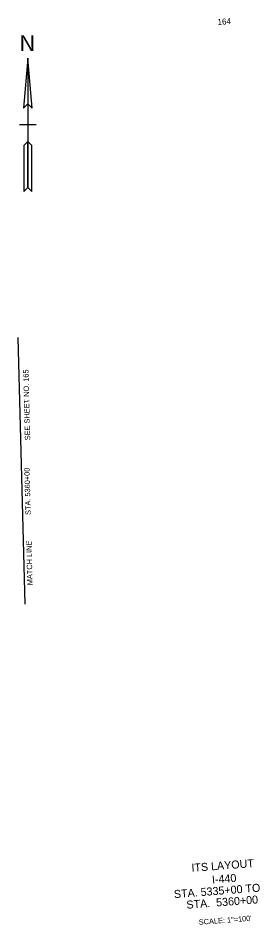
# Model space of a CAD drawing. Extents: x -200 to 1750512, y -325 to 653817.
# Drawn here: x 1749969 to 1750512, y 651778 to 653817 of the extents above; entities that cross this region are included whole.
import ezdxf

# ---------------------------------------------------------------- set-up
doc = ezdxf.new("R2010")
doc.units = 0
for name, color, linetype in [('DESIGN - CENTERLINE - Proposed Text', 7, 'Continuous'), ('DESIGN - SCRATCH - User 1', 7, 'Continuous'), ('DESIGN - SHEET - Corner Text', 7, 'Continuous'), ('ITS - CONST TEXT', 7, 'Continuous'), ('ITS - EXISITING WEATHER STATION', 7, 'Continuous'), ('ITS - EXISTING COMM CABLE', 7, 'Continuous'), ('ITS - EXISTING HAR', 7, 'Continuous')]:
    doc.layers.add(name, color=color, linetype=linetype)

msp = doc.modelspace()

# ---------------------------------------------------------------- linework, layer by layer
at = {"layer": 'DESIGN - CENTERLINE - Proposed Text'}
for p, q in [((1749990.2, 653576.8), (1749971.3, 653576.8)), ((1750009.1, 653576.8), (1749990.2, 653576.8))]:
    msp.add_line(p, q, dxfattribs=at)
msp.add_lwpolyline([(1749990.2, 653726.8), (1749980.4, 653614.2), (1749990.2, 653624), (1750000, 653614.2), (1749990.2, 653726.8), (1749990.2, 653435.9), (1749999.3, 653426.8), (1749999.3, 653530.3), (1749990.2, 653539.4), (1749981.1, 653530.3), (1749981.1, 653426.8), (1749990.2, 653435.9)], dxfattribs=at)
for points in [[(1749990.2, 653624), (1750000, 653614.2), (1749990.2, 653726.8)], [(1749981.1, 653426.8), (1749990.2, 653435.9), (1749990.2, 653539.4), (1749981.1, 653530.3)]]:
    msp.add_lwpolyline(points, close=True, dxfattribs=at)
at = {"layer": 'DESIGN - SCRATCH - User 1'}
for p, q in [((1750447.7, 651869.7), (1750447.7, 651869.7)), ((1750447.7, 651869.7), (1750447.7, 651869.7)), ((1750452.2, 651853.7), (1750452.2, 651853.7))]:
    msp.add_line(p, q, dxfattribs=at)
at = {"layer": 'ITS - EXISITING WEATHER STATION'}
msp.add_line((1750447.6, 651869.8), (1750447.6, 651869.8), dxfattribs=at)
msp.add_line((1750447.6, 651869.8), (1750447.6, 651869.8), dxfattribs=at)
at = {"layer": 'ITS - EXISTING COMM CABLE'}
msp.add_line((1749984.3, 652498.7), (1749968.6, 653098.4), dxfattribs=at)

# ---------------------------------------------------------------- texts
at = {"layer": 'DESIGN - CENTERLINE - Proposed Text'}
msp.add_text('N', height=35.4, dxfattribs=at).set_placement((1749972.1, 653742.9))
at = {"layer": 'DESIGN - SHEET - Corner Text'}
msp.add_text('164', height=13.5, rotation=4.3778, dxfattribs=at).set_placement((1750417.1, 653801.1))
at = {"layer": 'ITS - CONST TEXT'}
msp.add_text('SCALE: 1"=100\'', height=12, rotation=4.3778, dxfattribs=at).set_placement((1750374.9, 651777.9))
at = {"layer": 'ITS - EXISTING COMM CABLE'}
for s, p in [('SEE SHEET NO. 165 ', (1749995.8, 652867.6)), ('STA. 5360+00', (1749997, 652699.7)), ('MATCH LINE', (1750001.1, 652541.7))]:
    msp.add_text(s, height=12, rotation=91.4994, dxfattribs=at).set_placement(p)
at = {"layer": 'ITS - EXISTING HAR'}
for s, p in [('ITS LAYOUT', (1750358.7, 651897)), ('I-440', (1750404.8, 651870.6)), ('STA. 5335+00 TO', (1750319.2, 651837.9)), ('STA.  5360+00', (1750347.4, 651814))]:
    msp.add_text(s, height=18, rotation=4.3778, dxfattribs=at).set_placement(p)

doc.saveas('drawing.dxf')
